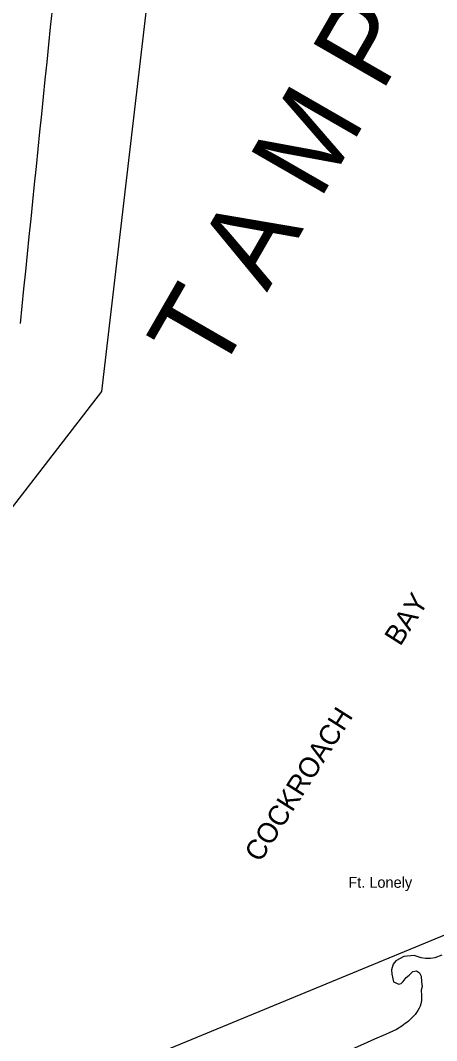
# Model space of a CAD drawing. Extents: x 380424 to 701066, y 1117407 to 1412949.
# Drawn here: x 463555 to 475997, y 1201019 to 1231495 of the extents above; entities that cross this region are included whole.
import ezdxf

# ---------------------------------------------------------------- set-up
doc = ezdxf.new("R2010")
doc.units = 0
for name, color, linetype in [('Bay Text', 7, 'Continuous'), ('Cities Incorporated Area', 7, 'Continuous'), ('County Boundary', 7, 'Continuous'), ('Geographic Features Text', 7, 'Continuous'), ('MASKS', 7, 'Continuous'), ('National Wildlife Refuge and Preserve Text', 7, 'Continuous')]:
    doc.layers.add(name, color=color, linetype=linetype)

msp = doc.modelspace()

# ---------------------------------------------------------------- linework, layer by layer
at = {"layer": 'Cities Incorporated Area'}
msp.add_lwpolyline([(476158, 1203574), (475942, 1203489), (475810, 1203468), (475663, 1203468), (475531, 1203489), (475330, 1203558), (475019, 1203532), (474782, 1203405), (474697, 1203299), (474650, 1203136), (474660, 1202999), (474713, 1202777), (474866, 1202703), (474935, 1202724), (474998, 1202782), (475088, 1202899), (475177, 1202978), (475283, 1203078), (475399, 1203104), (475483, 1203046), (475531, 1202941), (475547, 1202777), (475562, 1202635), (475536, 1202524)], dxfattribs=at)
for points in [[(463555, 1222439), (467218, 1255698), (468488, 1264116), (470378, 1278264), (469773, 1282680), (469300, 1286697), (465054, 1304493)], [(474802, 1201349), (464168, 1196771), (452442, 1191956), (449252, 1190509), (432918, 1183981), (418459, 1178014), (414265, 1176124), (413290, 1175710), (411459, 1175208), (408106, 1175208), (406895, 1175415), (406519, 1175578), (406519, 1175902), (406519, 1192990), (406519, 1200071), (406519, 1202693), (406519, 1205757), (406519, 1206245), (406792, 1206245), (411953, 1206341), (423709, 1206577), (438773, 1206577), (452080, 1206577)], [(475536, 1202524), (475525, 1202117), (475200, 1201644), (474802, 1201349)]]:
    msp.add_spline(points, degree=3, dxfattribs=at)
at = {"layer": 'County Boundary'}
for points in [[(446382, 1396286), (446884, 1354043), (446992, 1345273), (447031, 1316595), (468169, 1307048), (472729, 1278164), (471556, 1268120), (465979, 1220414), (453230, 1203914), (430730, 1203913), (430730, 1201663), (428480, 1197163), (417980, 1191913), (415730, 1191913), (415730, 1200913), (412730, 1203913), (406730, 1203913)], [(407327, 1177627), (411766, 1177580), (476748, 1204388), (477396, 1204378), (486744, 1204293), (531965, 1204479), (644544, 1204433)]]:
    msp.add_lwpolyline(points, dxfattribs=at)
at = {"layer": 'MASKS'}
for points in [[(463555, 1222439), (467218, 1255698), (468488, 1264116), (470378, 1278264), (469773, 1282680), (469300, 1286697), (465054, 1304493)], [(474802, 1201349), (464168, 1196771), (452442, 1191956), (449252, 1190509), (432918, 1183981), (418459, 1178014), (414265, 1176124), (413290, 1175710), (411459, 1175208), (408106, 1175208), (406895, 1175415), (406519, 1175578), (406519, 1175902), (406519, 1192990), (406519, 1200071), (406519, 1202693), (406519, 1205757), (406519, 1206245), (406792, 1206245), (411953, 1206341), (423709, 1206577), (438773, 1206577), (452080, 1206577)], [(475536, 1202524), (475525, 1202117), (475200, 1201644), (474802, 1201349)]]:
    msp.add_spline(points, degree=3, dxfattribs=at)

# ---------------------------------------------------------------- texts
at = {"layer": 'Bay Text'}
msp.add_text('T A M P A', height=2500, rotation=60.0686, dxfattribs=at).set_placement((469442, 1220780))
at = {"layer": 'Geographic Features Text'}
msp.add_text('Ft. Lonely', height=325, rotation=0.0004, dxfattribs=at).set_placement((473358, 1205583))
at = {"layer": 'National Wildlife Refuge and Preserve Text'}
for s, rotation, p in [('BAY', 57.6012, (474909, 1212777)), ('COCKROACH', 57.6013, (470725, 1206316))]:
    msp.add_text(s, height=600, rotation=rotation, dxfattribs=at).set_placement(p)

doc.saveas('drawing.dxf')
